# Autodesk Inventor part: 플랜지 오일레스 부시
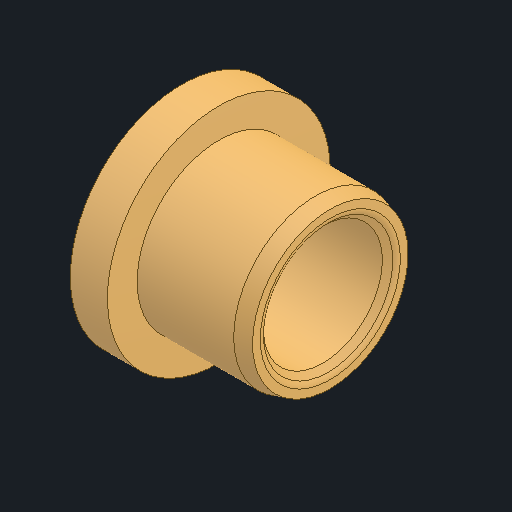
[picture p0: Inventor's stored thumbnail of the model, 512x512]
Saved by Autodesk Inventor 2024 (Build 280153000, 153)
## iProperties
Created: 2025-02
Part Number: 플랜지 오일레스 부시
Material: 구리, 합금
Document SubType Name: Modeling
Designer: kh_501
Density: 8.92 g/cm^3
Appearance: 기본값
Author: jhkim
Sending System: Autodesk Inventor 2025
Preprocessor: ST-DEVELOPER v20
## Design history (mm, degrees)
feature "솔리드1"
node "솔리드2"
